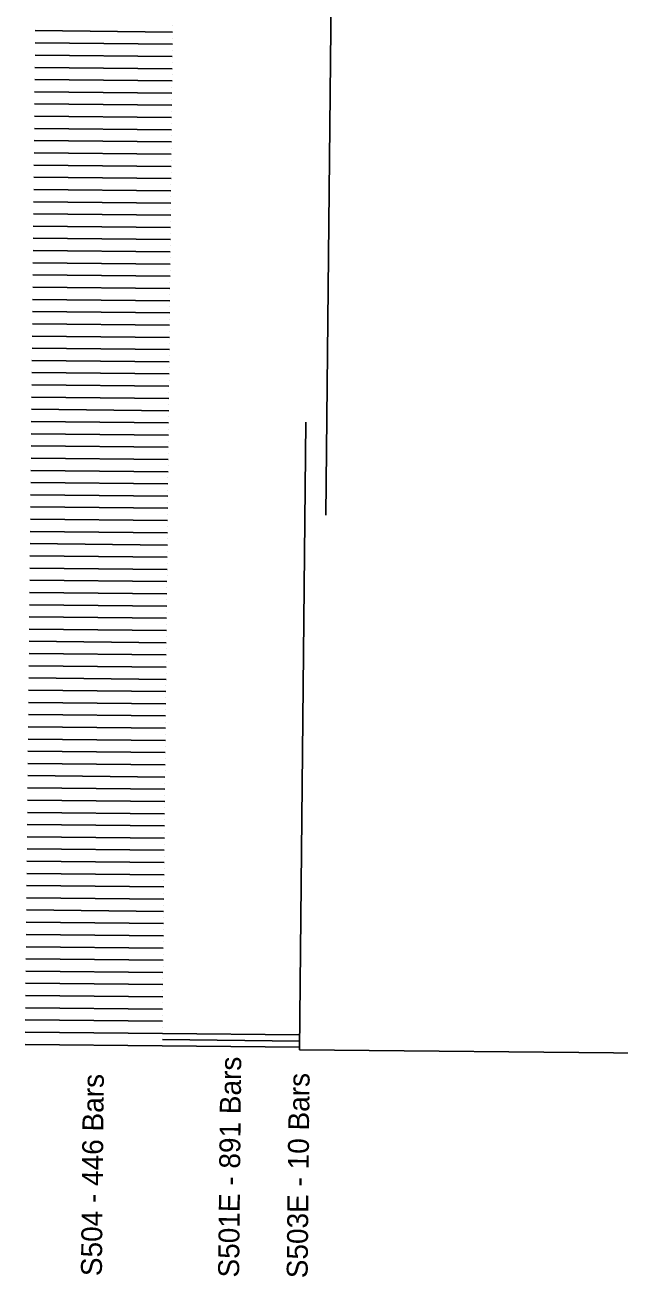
# Model space of a CAD drawing. Extents: x 632547 to 633311, y 380830 to 386139.
# Drawn here: x 633069.2 to 633126, y 380878.9 to 380998.5 of the extents above; entities that cross this region are included whole.
import ezdxf

# ---------------------------------------------------------------- set-up
doc = ezdxf.new("R2010")
doc.units = 0
for name, color, linetype in [('B_Border', 7, 'Continuous'), ('R_Border_Scale', 7, 'Continuous'), ('R_Wall', 7, 'Continuous')]:
    doc.layers.add(name, color=color, linetype=linetype)

msp = doc.modelspace()

# ---------------------------------------------------------------- linework, layer by layer
at = {"layer": 'B_Border'}
msp.add_line((633212.42, 380899.42), (633095.37, 380900.6), dxfattribs=at)
at = {"layer": 'R_Border_Scale'}
for p, q in [((633098.49, 381011.68), (633097.89, 380951.69)), ((633083.24, 380997.87), (633070.13, 380998.01)), ((633083.24, 380997.87), (633083.24, 380997.87)), ((633083.25, 380998.46), (633083.25, 380998.46)), ((633083.23, 380996.71), (633070.12, 380996.84)), ((633083.23, 380996.71), (633083.23, 380996.71)), ((633083.24, 380997.29), (633083.24, 380997.29)), ((633083.22, 380995.54), (633070.11, 380995.67)), ((633083.22, 380996.12), (633083.22, 380996.12)), ((633083.22, 380995.54), (633083.22, 380995.54)), ((633083.21, 380994.37), (633070.1, 380994.5)), ((633083.21, 380994.95), (633083.21, 380994.95)), ((633083.21, 380994.37), (633083.21, 380994.37)), ((633083.2, 380993.2), (633070.08, 380993.34)), ((633083.2, 380993.79), (633083.2, 380993.79)), ((633083.2, 380993.2), (633083.2, 380993.2)), ((633083.18, 380992.04), (633070.07, 380992.17)), ((633083.18, 380992.04), (633083.18, 380992.04)), ((633083.19, 380992.62), (633083.19, 380992.62)), ((633083.17, 380990.87), (633070.06, 380991)), ((633083.17, 380990.87), (633083.17, 380990.87)), ((633083.18, 380991.45), (633083.18, 380991.45)), ((633083.16, 380989.7), (633070.05, 380989.83)), ((633083.16, 380989.7), (633083.16, 380989.7)), ((633083.17, 380990.28), (633083.17, 380990.28)), ((633083.15, 380988.53), (633070.04, 380988.67)), ((633083.15, 380989.12), (633083.15, 380989.12)), ((633083.15, 380988.53), (633083.15, 380988.53)), ((633083.14, 380987.37), (633070.02, 380987.5)), ((633083.14, 380987.95), (633083.14, 380987.95)), ((633083.14, 380987.37), (633083.14, 380987.37)), ((633083.12, 380986.2), (633070.01, 380986.33)), ((633083.12, 380986.2), (633083.12, 380986.2)), ((633083.13, 380986.78), (633083.13, 380986.78)), ((633083.11, 380985.03), (633070, 380985.16)), ((633083.11, 380985.03), (633083.11, 380985.03)), ((633083.11, 380984.45), (633083.11, 380984.45)), ((633083.12, 380985.62), (633083.12, 380985.62)), ((633083.1, 380983.86), (633069.99, 380984)), ((633083.09, 380983.28), (633083.09, 380983.28)), ((633083.1, 380983.86), (633083.1, 380983.86)), ((633083.09, 380982.7), (633069.98, 380982.83)), ((633083.08, 380982.11), (633083.08, 380982.11)), ((633083.09, 380982.7), (633083.09, 380982.7)), ((633083.08, 380981.53), (633069.97, 380981.66)), ((633083.07, 380980.95), (633083.07, 380980.95)), ((633083.08, 380981.53), (633083.08, 380981.53)), ((633083.07, 380980.36), (633069.95, 380980.49)), ((633083.06, 380979.78), (633083.06, 380979.78)), ((633083.07, 380980.36), (633083.07, 380980.36)), ((633083.05, 380979.19), (633069.94, 380979.33)), ((633083.05, 380979.19), (633083.05, 380979.19)), ((633083.05, 380978.61), (633083.05, 380978.61)), ((633083.04, 380978.03), (633069.93, 380978.16)), ((633083.04, 380978.03), (633083.04, 380978.03)), ((633083.04, 380977.44), (633083.04, 380977.44)), ((633083.03, 380976.86), (633069.92, 380976.99)), ((633083.02, 380976.28), (633083.02, 380976.28)), ((633083.03, 380976.86), (633083.03, 380976.86)), ((633083.02, 380975.69), (633069.91, 380975.83)), ((633083.01, 380975.11), (633083.01, 380975.11)), ((633083.02, 380975.69), (633083.02, 380975.69)), ((633083.01, 380974.53), (633069.89, 380974.66)), ((633083, 380973.94), (633083, 380973.94)), ((633083.01, 380974.53), (633083.01, 380974.53)), ((633082.99, 380973.36), (633069.88, 380973.49)), ((633082.99, 380973.36), (633082.99, 380973.36)), ((633082.99, 380972.77), (633082.99, 380972.77)), ((633082.98, 380972.19), (633069.87, 380972.32)), ((633082.98, 380972.19), (633082.98, 380972.19)), ((633082.98, 380971.61), (633082.98, 380971.61)), ((633082.97, 380971.02), (633069.86, 380971.16)), ((633082.96, 380970.44), (633082.96, 380970.44)), ((633082.97, 380971.02), (633082.97, 380971.02)), ((633082.96, 380969.86), (633069.85, 380969.99)), ((633082.95, 380969.27), (633082.95, 380969.27)), ((633082.96, 380969.86), (633082.96, 380969.86)), ((633082.95, 380968.69), (633069.84, 380968.82)), ((633082.94, 380968.1), (633082.94, 380968.1)), ((633082.95, 380968.69), (633082.95, 380968.69)), ((633082.94, 380967.52), (633069.82, 380967.65)), ((633082.93, 380966.94), (633082.93, 380966.94)), ((633082.94, 380967.52), (633082.94, 380967.52)), ((633082.91, 380965.19), (633069.8, 380965.32)), ((633082.92, 380966.35), (633069.81, 380966.49)), ((633082.92, 380966.35), (633082.92, 380966.35)), ((633082.92, 380965.77), (633082.92, 380965.77)), ((633082.9, 380964.02), (633069.79, 380964.15)), ((633082.91, 380965.19), (633082.91, 380965.19)), ((633082.91, 380964.6), (633082.91, 380964.6)), ((633082.89, 380962.85), (633069.78, 380962.98)), ((633082.89, 380963.44), (633082.89, 380963.44)), ((633082.9, 380964.02), (633082.9, 380964.02)), ((633082.88, 380961.68), (633069.77, 380961.82)), ((633082.88, 380962.27), (633082.88, 380962.27)), ((633082.89, 380962.85), (633082.89, 380962.85)), ((633082.86, 380960.52), (633069.75, 380960.65)), ((633082.86, 380960.52), (633082.86, 380960.52)), ((633082.87, 380961.1), (633082.87, 380961.1)), ((633082.88, 380961.68), (633082.88, 380961.68)), ((633095.98, 380960.6), (633095.37, 380900.6)), ((633082.85, 380959.35), (633069.74, 380959.48)), ((633082.85, 380959.35), (633082.85, 380959.35)), ((633082.86, 380959.93), (633082.86, 380959.93)), ((633082.84, 380958.18), (633069.73, 380958.32)), ((633082.84, 380958.18), (633082.84, 380958.18)), ((633082.85, 380958.77), (633082.85, 380958.77)), ((633082.83, 380957.02), (633069.72, 380957.15)), ((633082.83, 380957.6), (633082.83, 380957.6)), ((633082.83, 380957.02), (633082.83, 380957.02)), ((633082.82, 380955.85), (633069.71, 380955.98)), ((633082.82, 380956.43), (633082.82, 380956.43)), ((633082.82, 380955.85), (633082.82, 380955.85)), ((633082.81, 380954.68), (633069.69, 380954.81)), ((633082.81, 380955.26), (633082.81, 380955.26)), ((633082.81, 380954.68), (633082.81, 380954.68)), ((633082.79, 380953.51), (633069.68, 380953.65)), ((633082.79, 380953.51), (633082.79, 380953.51)), ((633082.8, 380954.1), (633082.8, 380954.1)), ((633082.78, 380952.35), (633069.67, 380952.48)), ((633082.78, 380952.35), (633082.78, 380952.35)), ((633082.79, 380952.93), (633082.79, 380952.93)), ((633082.77, 380951.18), (633069.66, 380951.31)), ((633082.77, 380951.18), (633082.77, 380951.18)), ((633082.78, 380951.76), (633082.78, 380951.76)), ((633082.76, 380950.01), (633069.65, 380950.14)), ((633082.76, 380950.59), (633082.76, 380950.59)), ((633082.76, 380950.01), (633082.76, 380950.01)), ((633082.75, 380948.84), (633069.64, 380948.98)), ((633082.75, 380949.43), (633082.75, 380949.43)), ((633082.75, 380948.84), (633082.75, 380948.84)), ((633082.73, 380947.68), (633069.62, 380947.81)), ((633082.73, 380947.68), (633082.73, 380947.68)), ((633082.74, 380948.26), (633082.74, 380948.26)), ((633082.72, 380946.51), (633069.61, 380946.64)), ((633082.72, 380946.51), (633082.72, 380946.51)), ((633082.73, 380947.09), (633082.73, 380947.09)), ((633082.71, 380945.34), (633069.6, 380945.47)), ((633082.71, 380945.34), (633082.71, 380945.34)), ((633082.72, 380945.93), (633082.72, 380945.93)), ((633082.7, 380944.17), (633069.59, 380944.31)), ((633082.7, 380944.76), (633082.7, 380944.76)), ((633082.7, 380944.17), (633082.7, 380944.17)), ((633082.69, 380943.01), (633069.58, 380943.14)), ((633082.69, 380943.59), (633082.69, 380943.59)), ((633082.69, 380943.01), (633082.69, 380943.01)), ((633082.68, 380941.84), (633069.56, 380941.97)), ((633082.68, 380942.42), (633082.68, 380942.42)), ((633082.68, 380941.84), (633082.68, 380941.84)), ((633082.66, 380940.67), (633069.55, 380940.8)), ((633082.66, 380940.67), (633082.66, 380940.67)), ((633082.67, 380941.26), (633082.67, 380941.26)), ((633082.65, 380939.5), (633069.54, 380939.64)), ((633082.65, 380939.5), (633082.65, 380939.5)), ((633082.66, 380940.09), (633082.66, 380940.09)), ((633082.64, 380938.34), (633069.53, 380938.47)), ((633082.64, 380938.34), (633082.64, 380938.34)), ((633082.65, 380938.92), (633082.65, 380938.92)), ((633082.63, 380937.17), (633069.52, 380937.3)), ((633082.62, 380936.59), (633082.62, 380936.59)), ((633082.63, 380937.75), (633082.63, 380937.75)), ((633082.63, 380937.17), (633082.63, 380937.17)), ((633082.62, 380936), (633069.51, 380936.14)), ((633082.61, 380935.42), (633082.61, 380935.42)), ((633082.62, 380936), (633082.62, 380936)), ((633082.6, 380934.84), (633069.49, 380934.97)), ((633082.6, 380934.84), (633082.6, 380934.84)), ((633082.6, 380934.25), (633082.6, 380934.25)), ((633082.59, 380933.67), (633069.48, 380933.8)), ((633082.59, 380933.67), (633082.59, 380933.67)), ((633082.59, 380933.08), (633082.59, 380933.08)), ((633082.58, 380932.5), (633069.47, 380932.63)), ((633082.58, 380932.5), (633082.58, 380932.5)), ((633082.58, 380931.92), (633082.58, 380931.92)), ((633082.57, 380931.33), (633069.46, 380931.47)), ((633082.56, 380930.75), (633082.56, 380930.75)), ((633082.57, 380931.33), (633082.57, 380931.33)), ((633082.56, 380930.17), (633069.45, 380930.3)), ((633082.55, 380929.58), (633082.55, 380929.58)), ((633082.56, 380930.17), (633082.56, 380930.17)), ((633082.55, 380929), (633069.43, 380929.13)), ((633082.54, 380928.41), (633082.54, 380928.41)), ((633082.55, 380929), (633082.55, 380929)), ((633082.53, 380927.83), (633069.42, 380927.96)), ((633082.53, 380927.83), (633082.53, 380927.83)), ((633082.53, 380927.25), (633082.53, 380927.25)), ((633082.52, 380926.66), (633069.41, 380926.8)), ((633082.52, 380926.66), (633082.52, 380926.66)), ((633082.52, 380926.08), (633082.52, 380926.08)), ((633082.51, 380925.5), (633069.4, 380925.63)), ((633082.5, 380924.91), (633082.5, 380924.91)), ((633082.51, 380925.5), (633082.51, 380925.5)), ((633082.5, 380924.33), (633069.39, 380924.46)), ((633082.49, 380923.75), (633082.49, 380923.75)), ((633082.5, 380924.33), (633082.5, 380924.33)), ((633082.49, 380923.16), (633069.38, 380923.29)), ((633082.48, 380922.58), (633082.48, 380922.58)), ((633082.49, 380923.16), (633082.49, 380923.16)), ((633082.47, 380921.99), (633069.36, 380922.13)), ((633082.47, 380921.99), (633082.47, 380921.99)), ((633082.47, 380921.41), (633082.47, 380921.41)), ((633082.46, 380920.83), (633069.35, 380920.96)), ((633082.46, 380920.83), (633082.46, 380920.83)), ((633082.46, 380920.24), (633082.46, 380920.24)), ((633082.45, 380919.66), (633069.34, 380919.79)), ((633082.45, 380919.66), (633082.45, 380919.66)), ((633082.45, 380919.08), (633082.45, 380919.08)), ((633082.43, 380917.33), (633069.32, 380917.46)), ((633082.44, 380918.49), (633069.33, 380918.63)), ((633082.43, 380917.91), (633082.43, 380917.91)), ((633082.44, 380918.49), (633082.44, 380918.49)), ((633082.42, 380916.16), (633069.3, 380916.29)), ((633082.42, 380916.74), (633082.42, 380916.74)), ((633082.43, 380917.33), (633082.43, 380917.33)), ((633082.4, 380914.99), (633069.29, 380915.12)), ((633082.41, 380915.57), (633082.41, 380915.57)), ((633082.42, 380916.16), (633082.42, 380916.16)), ((633082.39, 380913.82), (633069.28, 380913.96)), ((633082.4, 380914.99), (633082.4, 380914.99)), ((633082.4, 380914.41), (633082.4, 380914.41)), ((633082.38, 380912.66), (633069.27, 380912.79)), ((633082.38, 380912.66), (633082.38, 380912.66)), ((633082.39, 380913.82), (633082.39, 380913.82)), ((633082.39, 380913.24), (633082.39, 380913.24)), ((633082.37, 380911.49), (633069.26, 380911.62)), ((633082.37, 380912.07), (633082.37, 380912.07)), ((633082.37, 380911.49), (633082.37, 380911.49)), ((633082.36, 380910.32), (633069.25, 380910.45)), ((633082.36, 380910.9), (633082.36, 380910.9)), ((633082.36, 380910.32), (633082.36, 380910.32)), ((633082.34, 380909.15), (633069.23, 380909.29)), ((633082.34, 380909.15), (633082.34, 380909.15)), ((633082.35, 380909.74), (633082.35, 380909.74)), ((633082.33, 380907.99), (633069.22, 380908.12)), ((633082.33, 380907.99), (633082.33, 380907.99)), ((633082.34, 380908.57), (633082.34, 380908.57)), ((633082.32, 380906.82), (633069.21, 380906.95)), ((633082.32, 380906.82), (633082.32, 380906.82)), ((633082.33, 380907.4), (633082.33, 380907.4)), ((633082.31, 380905.65), (633069.2, 380905.78)), ((633082.31, 380905.65), (633082.31, 380905.65)), ((633082.32, 380906.24), (633082.32, 380906.24)), ((633082.3, 380904.48), (633069.19, 380904.62)), ((633082.3, 380905.07), (633082.3, 380905.07)), ((633082.3, 380904.48), (633082.3, 380904.48)), ((633082.29, 380903.32), (633069.17, 380903.45)), ((633082.29, 380903.9), (633082.29, 380903.9)), ((633082.29, 380903.32), (633082.29, 380903.32)), ((633082.27, 380902.15), (633069.16, 380902.28)), ((633095.39, 380902.02), (633082.27, 380902.15)), ((633082.27, 380902.15), (633082.27, 380902.15)), ((633082.28, 380902.73), (633082.28, 380902.73)), ((633082.26, 380900.98), (633069.15, 380901.11)), ((633095.37, 380900.85), (633082.26, 380900.98)), ((633082.26, 380900.98), (633082.26, 380900.98)), ((633095.38, 380901.43), (633082.27, 380901.57)), ((633082.27, 380901.57), (633082.27, 380901.57))]:
    msp.add_line(p, q, dxfattribs=at)

# ---------------------------------------------------------------- texts
at = {"layer": 'R_Wall'}
for s, p in [('S501E - 891 Bars', (633089.6, 380878.82)), ('S504 - 446 Bars', (633076.49, 380878.95)), ('S503E - 10 Bars', (633096.15, 380878.75))]:
    msp.add_text(s, height=2, rotation=89.4304, dxfattribs=at).set_placement(p)

doc.saveas('drawing.dxf')
